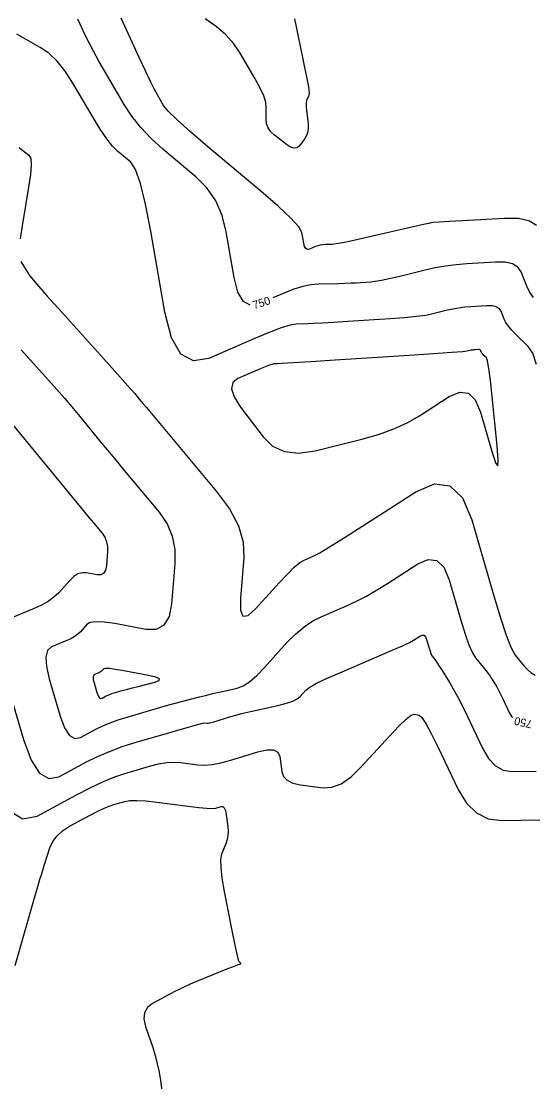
# Model space of a CAD drawing. Extents: x 2082232 to 2083549, y 592624 to 593832.
# Drawn here: x 2082848.9 to 2082893.7, y 592676 to 592768.7 of the extents above; entities that cross this region are included whole.
import ezdxf

# ---------------------------------------------------------------- set-up
doc = ezdxf.new("R2010")
doc.units = 0
doc.layers.add('DT_X_Contour_Major', color=7, linetype='Continuous')
doc.layers.add('DT_X_Contour_Minor', color=7, linetype='Continuous')

msp = doc.modelspace()

# ---------------------------------------------------------------- linework, layer by layer
at = {"layer": 'DT_X_Contour_Major'}
for points in [[(2082868.984, 592743.86), (2082868.385, 592744.187), (2082867.911, 592744.992), (2082867.58, 592746.263), (2082866.891, 592750.276), (2082866.53, 592751.705), (2082865.964, 592752.984), (2082865.193, 592754.113), (2082864.216, 592755.092), (2082861.339, 592757.502), (2082860.317, 592758.425), (2082859.413, 592759.384), (2082858.624, 592760.379), (2082857.951, 592761.411), (2082856.313, 592764.213), (2082855.744, 592765.201), (2082855.265, 592766.063), (2082854.878, 592766.8), (2082854.582, 592767.412), (2082853.912, 592768.875)], [(2082893.757, 592744.524), (2082893.425, 592745.029), (2082893.189, 592745.514), (2082892.689, 592746.782), (2082892.407, 592747.191), (2082891.936, 592747.467), (2082891.277, 592747.61), (2082890.43, 592747.62), (2082887.919, 592747.47), (2082886.986, 592747.394), (2082886.069, 592747.277), (2082885.168, 592747.12), (2082884.284, 592746.924), (2082881.948, 592746.345), (2082881.139, 592746.152), (2082880.465, 592746.009), (2082879.927, 592745.914), (2082879.523, 592745.867), (2082878.627, 592745.809), (2082878.253, 592745.788), (2082877.802, 592745.769), (2082877.273, 592745.752), (2082876.669, 592745.736), (2082874.953, 592745.696), (2082874.286, 592745.637), (2082873.571, 592745.492), (2082872.807, 592745.26), (2082871.996, 592744.942), (2082870.963, 592744.495)], [(2082848.947, 592739.95), (2082850.813, 592737.882), (2082851.817, 592736.76), (2082852.722, 592735.729), (2082853.527, 592734.79), (2082854.233, 592733.942), (2082855.983, 592731.802), (2082856.657, 592730.981), (2082857.367, 592730.122), (2082858.112, 592729.225), (2082858.893, 592728.291), (2082861.023, 592725.748), (2082861.708, 592724.75), (2082862.166, 592723.664), (2082862.396, 592722.49), (2082862.398, 592721.228), (2082862.101, 592717.745), (2082861.876, 592716.626), (2082861.425, 592715.88), (2082860.747, 592715.508), (2082859.842, 592715.509), (2082857.127, 592716.01), (2082856.21, 592716.146), (2082855.496, 592716.177), (2082854.985, 592716.103), (2082854.677, 592715.925), (2082854.125, 592715.309), (2082853.887, 592715.084), (2082853.587, 592714.87), (2082853.226, 592714.668), (2082852.803, 592714.477), (2082851.593, 592713.982), (2082851.24, 592713.668), (2082851.091, 592713.095), (2082851.145, 592712.265), (2082851.402, 592711.176), (2082852.359, 592707.93), (2082852.739, 592706.9), (2082853.159, 592706.244), (2082853.622, 592705.964), (2082854.126, 592706.058), (2082855.525, 592706.808), (2082856.086, 592707.084), (2082856.719, 592707.349), (2082857.426, 592707.604), (2082858.205, 592707.848), (2082860.38, 592708.485), (2082861.162, 592708.711), (2082861.874, 592708.911), (2082862.517, 592709.087), (2082863.092, 592709.237), (2082864.531, 592709.603), (2082865.063, 592709.736), (2082865.58, 592709.862), (2082866.082, 592709.98), (2082866.569, 592710.091), (2082867.846, 592710.375), (2082868.356, 592710.569), (2082868.928, 592710.938), (2082869.562, 592711.482), (2082870.257, 592712.201), (2082872.195, 592714.35), (2082872.931, 592715.099), (2082873.688, 592715.731), (2082874.464, 592716.248), (2082875.259, 592716.649), (2082877.408, 592717.564), (2082878.236, 592717.945), (2082879.111, 592718.399), (2082880.033, 592718.927), (2082881, 592719.53), (2082883.643, 592721.236), (2082884.558, 592721.629), (2082885.321, 592721.53), (2082885.933, 592720.939), (2082886.394, 592719.855), (2082887.42, 592716.309), (2082887.788, 592715.106), (2082888.123, 592714.16), (2082888.424, 592713.468), (2082888.692, 592713.032), (2082889.361, 592712.21), (2082889.595, 592711.917), (2082889.797, 592711.653), (2082889.965, 592711.42), (2082890.101, 592711.216), (2082890.418, 592710.713), (2082890.548, 592710.493), (2082890.702, 592710.207), (2082890.88, 592709.857), (2082891.081, 592709.442), (2082891.648, 592708.25), (2082891.878, 592707.859), (2082891.92, 592707.815)]]:
    msp.add_lwpolyline(points, dxfattribs=at)
at = {"layer": 'DT_X_Contour_Minor'}
for points in [[(2082894.043, 592750.826), (2082893.364, 592751.225), (2082892.413, 592751.431), (2082891.189, 592751.446), (2082887.565, 592751.229), (2082886.374, 592751.158), (2082885.519, 592751.106), (2082885, 592751.073), (2082884.817, 592751.06), (2082884.777, 592751.05), (2082884.611, 592751.011), (2082884.143, 592750.904), (2082883.373, 592750.728), (2082879.039, 592749.738), (2082877.941, 592749.492), (2082877.091, 592749.316), (2082876.491, 592749.208), (2082876.14, 592749.168), (2082875.537, 592749.154), (2082875.315, 592749.139), (2082875.1, 592749.104), (2082874.893, 592749.049), (2082874.694, 592748.974), (2082874.172, 592748.748), (2082873.994, 592748.718), (2082873.849, 592748.797), (2082873.738, 592748.986), (2082873.66, 592749.283), (2082873.499, 592750.222), (2082873.229, 592750.712), (2082872.541, 592751.477), (2082871.435, 592752.517), (2082869.909, 592753.832), (2082865.285, 592757.705), (2082863.742, 592759.02), (2082862.581, 592760.059), (2082861.802, 592760.824), (2082861.405, 592761.313), (2082860.857, 592762.249), (2082860.604, 592762.717), (2082860.255, 592763.419), (2082859.811, 592764.354), (2082859.271, 592765.523), (2082857.703, 592768.95)], [(2082872.858, 592768.897), (2082873.386, 592766.368), (2082873.567, 592765.497), (2082873.713, 592764.781), (2082873.826, 592764.221), (2082873.904, 592763.817), (2082874.067, 592762.945), (2082874.114, 592762.648), (2082874.132, 592762.41), (2082874.121, 592762.231), (2082874.082, 592762.113), (2082873.939, 592761.875), (2082873.897, 592761.745), (2082873.88, 592761.533), (2082873.888, 592761.24), (2082873.919, 592760.864), (2082874.037, 592759.755), (2082874.053, 592759.36), (2082874.013, 592759.009), (2082873.918, 592758.702), (2082873.766, 592758.437), (2082873.288, 592757.789), (2082873.083, 592757.615), (2082872.825, 592757.576), (2082872.515, 592757.673), (2082872.153, 592757.907), (2082871.118, 592758.711), (2082870.78, 592759.024), (2082870.541, 592759.36), (2082870.402, 592759.718), (2082870.362, 592760.1), (2082870.389, 592761.148), (2082870.337, 592761.599), (2082870.158, 592762.163), (2082869.854, 592762.84), (2082869.424, 592763.632), (2082868.109, 592765.896), (2082867.548, 592766.719), (2082866.85, 592767.49), (2082866.015, 592768.21), (2082865.043, 592768.879)], [(2082894.027, 592738.655), (2082893.696, 592739.654), (2082893.314, 592740.25), (2082892.229, 592741.304), (2082891.859, 592741.682), (2082891.566, 592742.029), (2082891.348, 592742.342), (2082891.206, 592742.623), (2082890.927, 592743.328), (2082890.77, 592743.555), (2082890.508, 592743.709), (2082890.142, 592743.789), (2082889.67, 592743.794), (2082888.273, 592743.711), (2082887.754, 592743.668), (2082887.244, 592743.603), (2082886.743, 592743.516), (2082886.251, 592743.407), (2082884.951, 592743.085), (2082884.352, 592742.968), (2082883.529, 592742.859), (2082882.482, 592742.758), (2082881.212, 592742.664), (2082877.528, 592742.425), (2082876.271, 592742.346), (2082875.266, 592742.287), (2082874.512, 592742.248), (2082874.009, 592742.229), (2082873.003, 592742.205), (2082872.489, 592742.118), (2082871.7, 592741.873), (2082870.636, 592741.47), (2082869.298, 592740.91), (2082865.364, 592739.207), (2082864.016, 592738.98), (2082862.922, 592739.578), (2082862.084, 592740.999), (2082861.5, 592743.244), (2082860.283, 592750.329), (2082859.831, 592752.698), (2082859.387, 592754.492), (2082858.951, 592755.71), (2082858.523, 592756.353), (2082857.392, 592757.3), (2082856.939, 592757.752), (2082856.427, 592758.396), (2082855.855, 592759.234), (2082855.226, 592760.265), (2082853.467, 592763.271), (2082852.794, 592764.312), (2082852.093, 592765.181), (2082851.364, 592765.876), (2082850.607, 592766.399), (2082848.551, 592767.563)], [(2082848.766, 592757.653), (2082849.091, 592757.366), (2082849.625, 592756.979), (2082849.774, 592756.694), (2082849.818, 592756.13), (2082849.758, 592755.287), (2082849.594, 592754.164), (2082849.017, 592750.798), (2082848.849, 592749.657)], [(2082848.919, 592747.688), (2082849.364, 592746.906), (2082849.683, 592746.459), (2082850.304, 592745.703), (2082851.228, 592744.638), (2082852.455, 592743.265), (2082856.13, 592739.193), (2082857.355, 592737.833), (2082858.273, 592736.809), (2082858.885, 592736.12), (2082859.191, 592735.766), (2082859.598, 592735.269), (2082859.895, 592734.91), (2082860.483, 592734.205), (2082861.362, 592733.155), (2082862.53, 592731.759), (2082866.033, 592727.578), (2082867.168, 592726.039), (2082867.947, 592724.561), (2082868.368, 592723.142), (2082868.433, 592721.783), (2082868.131, 592718.239), (2082868.128, 592717.183), (2082868.347, 592716.674), (2082868.788, 592716.712), (2082869.451, 592717.296), (2082871.512, 592719.583), (2082872.229, 592720.351), (2082872.833, 592720.939), (2082873.324, 592721.346), (2082873.701, 592721.573), (2082874.558, 592721.938), (2082875.061, 592722.2), (2082875.925, 592722.714), (2082877.151, 592723.48), (2082878.74, 592724.496), (2082883.458, 592727.542), (2082885.092, 592728.245), (2082886.456, 592728.068), (2082887.549, 592727.012), (2082888.371, 592725.077), (2082890.203, 592718.744), (2082890.841, 592716.621), (2082891.381, 592715), (2082891.823, 592713.883), (2082892.167, 592713.269), (2082892.954, 592712.303), (2082893.257, 592711.973), (2082893.575, 592711.707), (2082893.909, 592711.505)], [(2082870.107, 592732.334), (2082870.945, 592731.524), (2082871.982, 592731.054), (2082873.218, 592730.924), (2082874.652, 592731.134), (2082878.743, 592732.145), (2082880.208, 592732.557), (2082881.535, 592733.032), (2082882.725, 592733.571), (2082883.778, 592734.174), (2082886.401, 592735.868), (2082887.31, 592736.258), (2082888.068, 592736.16), (2082888.676, 592735.573), (2082889.133, 592734.497), (2082890.152, 592730.976), (2082890.465, 592730.022), (2082890.642, 592729.802), (2082890.682, 592730.315), (2082890.585, 592731.561), (2082890.145, 592735.863), (2082889.99, 592737.285), (2082889.856, 592738.323), (2082889.742, 592738.978), (2082889.649, 592739.25), (2082889.429, 592739.464), (2082889.354, 592739.54), (2082889.295, 592739.611), (2082889.251, 592739.674), (2082889.222, 592739.731), (2082889.165, 592739.874), (2082889.134, 592739.92), (2082889.081, 592739.951), (2082889.006, 592739.967), (2082888.911, 592739.968), (2082888.628, 592739.951), (2082888.523, 592739.943), (2082888.419, 592739.93), (2082888.318, 592739.912), (2082888.218, 592739.89), (2082887.954, 592739.825), (2082887.565, 592739.784), (2082886.592, 592739.709), (2082885.038, 592739.602), (2082882.902, 592739.461), (2082876.428, 592739.042), (2082874.29, 592738.904), (2082872.731, 592738.804), (2082871.751, 592738.744), (2082871.35, 592738.722), (2082871.053, 592738.715), (2082870.878, 592738.679), (2082870.574, 592738.576), (2082870.141, 592738.405), (2082869.579, 592738.168), (2082867.911, 592737.446), (2082867.456, 592737.086), (2082867.342, 592736.55), (2082867.569, 592735.836), (2082868.137, 592734.945), (2082870.107, 592732.334)], [(2082848.195, 592733.431), (2082849.275, 592732.118), (2082852.368, 592728.336), (2082853.419, 592727.053), (2082854.251, 592726.039), (2082854.863, 592725.296), (2082855.256, 592724.822), (2082856.014, 592723.918), (2082856.257, 592723.563), (2082856.42, 592723.177), (2082856.502, 592722.76), (2082856.502, 592722.311), (2082856.397, 592721.073), (2082856.317, 592720.675), (2082856.156, 592720.409), (2082855.915, 592720.277), (2082855.594, 592720.278), (2082854.629, 592720.456), (2082854.267, 592720.464), (2082853.906, 592720.355), (2082853.545, 592720.129), (2082853.184, 592719.787), (2082852.224, 592718.716), (2082851.81, 592718.324), (2082851.289, 592717.953), (2082850.661, 592717.6), (2082849.925, 592717.268), (2082847.819, 592716.407)], [(2082847.488, 592711.526), (2082849.153, 592705.878), (2082849.813, 592704.086), (2082850.545, 592702.946), (2082851.35, 592702.458), (2082852.226, 592702.621), (2082854.66, 592703.926), (2082855.615, 592704.4), (2082856.657, 592704.844), (2082857.786, 592705.258), (2082859, 592705.641), (2082862.354, 592706.623), (2082863.463, 592706.944), (2082864.277, 592707.17), (2082864.795, 592707.302), (2082865.016, 592707.339), (2082865.213, 592707.313), (2082865.329, 592707.321), (2082865.529, 592707.362), (2082865.812, 592707.437), (2082866.18, 592707.545), (2082867.274, 592707.881), (2082867.724, 592708.011), (2082868.255, 592708.151), (2082868.865, 592708.3), (2082869.557, 592708.458), (2082871.507, 592708.893), (2082872.17, 592709.062), (2082872.699, 592709.243), (2082873.092, 592709.436), (2082873.35, 592709.641), (2082873.857, 592710.204), (2082874.185, 592710.457), (2082874.787, 592710.795), (2082875.665, 592711.218), (2082876.817, 592711.725), (2082880.257, 592713.191), (2082881.412, 592713.689), (2082882.298, 592714.083), (2082882.914, 592714.375), (2082883.261, 592714.564), (2082883.827, 592714.929), (2082884.024, 592715.014), (2082884.187, 592714.993), (2082884.318, 592714.866), (2082884.417, 592714.634), (2082884.637, 592713.874), (2082884.716, 592713.616), (2082884.788, 592713.413), (2082884.852, 592713.265), (2082884.909, 592713.171), (2082885.053, 592712.995), (2082885.134, 592712.883), (2082885.271, 592712.678), (2082885.463, 592712.381), (2082885.711, 592711.991), (2082886.444, 592710.827), (2082886.746, 592710.316), (2082887.103, 592709.656), (2082887.514, 592708.846), (2082887.979, 592707.886), (2082889.291, 592705.128), (2082889.822, 592704.224), (2082890.43, 592703.582), (2082891.114, 592703.201), (2082891.876, 592703.082), (2082894.011, 592703.111)], [(2082860.63, 592710.899), (2082861.007, 592711.039), (2082861.042, 592711.183), (2082860.736, 592711.329), (2082860.09, 592711.479), (2082857.911, 592711.881), (2082857.189, 592712.005), (2082856.658, 592712.077), (2082856.318, 592712.096), (2082856.169, 592712.063), (2082856.025, 592711.902), (2082855.963, 592711.844), (2082855.885, 592711.788), (2082855.791, 592711.735), (2082855.681, 592711.686), (2082855.366, 592711.557), (2082855.274, 592711.475), (2082855.235, 592711.326), (2082855.249, 592711.11), (2082855.316, 592710.826), (2082855.565, 592709.981), (2082855.664, 592709.713), (2082855.774, 592709.543), (2082855.894, 592709.47), (2082856.025, 592709.494), (2082856.389, 592709.689), (2082856.535, 592709.761), (2082856.7, 592709.83), (2082856.884, 592709.897), (2082857.087, 592709.96), (2082857.653, 592710.126), (2082857.908, 592710.198), (2082858.245, 592710.289), (2082858.667, 592710.399), (2082859.172, 592710.528), (2082860.63, 592710.899)], [(2082847.931, 592699.648), (2082849.077, 592698.952), (2082850.326, 592699.185), (2082853.795, 592701.044), (2082855.034, 592701.684), (2082856.151, 592702.209), (2082857.146, 592702.619), (2082858.018, 592702.914), (2082860.18, 592703.547), (2082860.959, 592703.745), (2082861.673, 592703.866), (2082862.323, 592703.909), (2082862.908, 592703.875), (2082864.382, 592703.679), (2082864.978, 592703.649), (2082865.658, 592703.705), (2082866.423, 592703.849), (2082867.273, 592704.079), (2082869.652, 592704.809), (2082870.441, 592704.988), (2082871.024, 592704.978), (2082871.399, 592704.777), (2082871.568, 592704.387), (2082871.744, 592703.093), (2082871.895, 592702.656), (2082872.216, 592702.316), (2082872.708, 592702.073), (2082873.371, 592701.926), (2082875.365, 592701.664), (2082876.135, 592701.703), (2082876.948, 592702.019), (2082877.803, 592702.611), (2082878.702, 592703.478), (2082881.157, 592706.159), (2082881.984, 592707.035), (2082882.622, 592707.651), (2082883.071, 592708.007), (2082883.331, 592708.103), (2082883.775, 592708.013), (2082884.002, 592707.812), (2082884.352, 592707.274), (2082884.824, 592706.401), (2082885.418, 592705.191), (2082887.166, 592701.518), (2082887.896, 592700.315), (2082888.777, 592699.461), (2082889.807, 592698.955), (2082890.987, 592698.798), (2082894.333, 592698.845)], [(2082848.409, 592686.123), (2082849.646, 592690.415), (2082850.052, 592691.825), (2082850.343, 592692.834), (2082850.517, 592693.442), (2082850.577, 592693.651), (2082850.581, 592693.672), (2082850.606, 592693.752), (2082850.678, 592693.976), (2082850.796, 592694.343), (2082850.96, 592694.855), (2082851.462, 592696.41), (2082851.71, 592696.966), (2082852.079, 592697.465), (2082852.569, 592697.909), (2082853.179, 592698.296), (2082854.966, 592699.255), (2082855.599, 592699.582), (2082856.154, 592699.847), (2082856.633, 592700.049), (2082857.036, 592700.187), (2082858.007, 592700.471), (2082858.455, 592700.547), (2082859.069, 592700.562), (2082859.851, 592700.517), (2082860.8, 592700.41), (2082863.552, 592700.044), (2082864.477, 592699.931), (2082865.187, 592699.865), (2082865.682, 592699.847), (2082865.963, 592699.876), (2082866.425, 592700.018), (2082866.584, 592700.015), (2082866.712, 592699.899), (2082866.811, 592699.67), (2082866.88, 592699.329), (2082867.024, 592698.267), (2082867.054, 592697.875), (2082867.035, 592697.496), (2082866.968, 592697.129), (2082866.853, 592696.774), (2082866.481, 592695.845), (2082866.39, 592695.38), (2082866.398, 592694.682), (2082866.505, 592693.751), (2082866.709, 592692.586), (2082867.385, 592689.169), (2082867.612, 592688.043), (2082867.784, 592687.227), (2082867.902, 592686.722), (2082867.965, 592686.527), (2082868.062, 592686.421), (2082868.094, 592686.384), (2082868.116, 592686.353), (2082868.129, 592686.328), (2082868.132, 592686.309), (2082868.129, 592686.266), (2082868.122, 592686.251), (2082868.104, 592686.237), (2082868.075, 592686.223), (2082868.034, 592686.211), (2082867.911, 592686.179), (2082867.78, 592686.132), (2082867.478, 592686.013), (2082867.005, 592685.824), (2082866.362, 592685.563), (2082864.42, 592684.774), (2082863.715, 592684.478), (2082863.057, 592684.181), (2082862.446, 592683.883), (2082861.881, 592683.585), (2082860.438, 592682.79), (2082859.994, 592682.442), (2082859.744, 592681.995), (2082859.687, 592681.448), (2082859.824, 592680.801), (2082860.448, 592678.945), (2082860.665, 592678.243), (2082860.85, 592677.528), (2082861.002, 592676.801), (2082861.121, 592676.06), (2082861.395, 592674.07)]]:
    msp.add_lwpolyline(points, dxfattribs=at)

# ---------------------------------------------------------------- texts
at = {"layer": 'DT_X_Contour_Major'}
for rotation, p in [(17.78418, (2082869.325, 592743.494)), (167.06601, (2082893.701, 592707.524))]:
    msp.add_text('750', height=0.7, rotation=rotation, dxfattribs=at).set_placement(p)

doc.saveas('drawing.dxf')
